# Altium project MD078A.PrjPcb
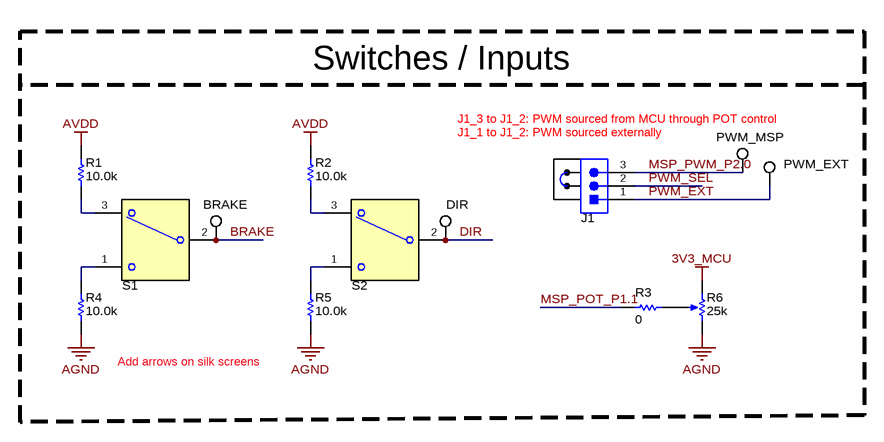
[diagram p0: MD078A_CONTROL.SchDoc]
CopyrightYear: 2023; PCB_Layout: Hong Ze Khor; PCB_Rev: A; PRJ_Customer: Public Release; PRJ_Engineer: Hong Ze Khor; PRJ_Number: MD078; PRJ_Title: MCT8314ZEVM; ProjectVariant: EVM_Orderable; SCH_Rev: A; TechSupport: http://www.ti.com/support; TID: N/A
5 sheets, 157 parts. Net scope: global (net labels, ports and power ports of the same name join across sheets).
Board file: MD078A.PcbDoc
Sheets:
  MD078A_CONTROL.SchDoc
  MD078A_DRIVER.SchDoc
  MD078A_HARDWARE.SchDoc
  MD078A_INTERFACE.SchDoc
  MD078A_POWER_AND_CONNECTORS.SchDoc

## Sheet MD078A_CONTROL.SchDoc
size 431 x 279 mm; Date: Not shown in title block; ApprovedBy: Not shown in title block; CheckedBy: Not shown in title block; Author: Not shown in title block; CompanyName: Not shown in title block; Engineer: Not shown in title block; Organization: Not shown in title block; Address1: Not shown in title block; Address2: Not shown in title block; Address3: Not shown in title block; Address4: Not shown in title block; DocumentNumber: 1; Revision: Use project parameter SCH_Rev; SheetNumber: 2; SheetTotal: 5; PageSetup: Record=PageOptions¦CenterHorizontal=True¦CenterVertical=True¦PrintScale=1.00¦XCorrection=1.00¦YCorrection=1.00¦PrintKind=0¦BorderSize=5000000¦LeftOffset=0¦BottomOffset=0¦Orientation=2¦PaperLength=1000¦PaperWidth=1000¦Scale=100¦PaperSource=15¦PrintQuality=600¦MediaType=1¦DitherType=10¦PaperKind=Letter¦PrintScaleMode=1

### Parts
J1  Header_3x1  [PBC03SAAN]  (value not drawn)
R1  ValueDisplayed: 10.0k  [0603]  (hidden comment: RC0603FR-0710KL)
R2  ValueDisplayed: 10.0k  [0603]  (hidden comment: RC0603FR-0710KL)
R3  ValueDisplayed: 0  [0603L]  (hidden comment: ERJ-3GEY0R00V)
R4  ValueDisplayed: 10.0k  [0603]  (hidden comment: RC0603FR-0710KL)
R5  ValueDisplayed: 10.0k  [0603]  (hidden comment: RC0603FR-0710KL)
R6  value 25k  [Bourns_3352T]  (hidden comment: 3352T-1-253LF)
S1  SW_SPDT_COM2_1_3  [SW_B12AP]  (value not drawn)
S2  SW_SPDT_COM2_1_3  [SW_B12AP]  (value not drawn)
SH-J1  SNT-100-BK-G  [SNT-100-BK-G]  (value not drawn)
TP1  PWM_MSP  [Keystone5002]
TP2  PWM_EXT  [Keystone5002]
TP3  BRAKE  [Keystone5002]
TP4  DIR  [Keystone5002]

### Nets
3V3_MCU: R6.1(CCW)
AGND: R4.1 R5.1 R6.3(CW)
AVDD: R1.2 R2.2
BRAKE: S1.2(COM) TP3.1
DIR: S2.2(COM) TP4.1
MSP_POT_P1.1: R3.1
MSP_PWM_P2.0: J1.3 TP1.1
PWM_EXT: J1.1 TP2.1
PWM_SEL: J1.2
NetR1_1: R1.1 S1.3
NetR2_1: R2.1 S2.3
NetR3_2: R3.2 R6.2(WIPER)
NetR4_2: R4.2 S1.1
NetR5_2: R5.2 S2.1

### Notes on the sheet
- Switches / Inputs
- J1_1 to J1_2: PWM sourced externally
- J1_3 to J1_2: PWM sourced from MCU through POT control
- Add arrows on silk screens

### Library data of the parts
J1 = CMP-0002334-1: Header, 100mil, 3x1, Gold, TH; Manufacturer: Sullins Connector Solutions; CNHeader: TRUE; CT: FALSE; Green_Lifecycle: Not Set; Green_REACh: Incomplete
R1 R2 R4 R5 = CMP-0022746-5: RES, 10.0 k, 1%, 0.1 W, 0603; Manufacturer: Yageo; Power_W: 100mW; TempCo: 100 ppm/C; Value_Code: 10k0; Value: 10.0k; EIA_Code: E96; Res_ohm: 10k; SizeX_mm: 1.6; SizeY_mm: 0.8; SizeZ_mm: 1; Value2: 0.1W; SizeArea_mm2: 1.28; AEC Qualified: N; VDC_V: 75V; AEC Category: Q200; SizeAreaWB_mm2: 4.68
R3 = CMP-0025874-4: RES, 0, 5%, 0.1 W, AEC-Q200 Grade 0, 0603; Manufacturer: Panasonic; Power_W: 100mW; TempCo: 600 ppm/C; Value_Code: 0000; Value: 0; EIA_Code: E24; SizeX_mm: 1.6; SizeY_mm: 0.8; SizeZ_mm: 1; Value2: 0.1W; SizeArea_mm2: 1.28; AEC Qualified: Y; VDC_V: 50V; AEC Category: Q200; SizeAreaWB_mm2: 4.68
R6 = CMP-0001776-2: Trimmer Potentiometer, 25kohm, 0.5W, TH; Manufacturer: Bourns
S1 S2 = CMP-0002155-2: SWITCH TOGGLE SPDT 0.4VA 28V; PartNumber: B12AP; Manufacturer: NKK Switches; SwitchFunction: On-On; PositionCount: 2; CurrentRating_mA: 100A
SH-J1 = CMP-0003623-3: Shunt, 100mil, Gold plated, Black; Alternate PartNumber: 969102-0000-DA; Manufacturer: Samtec; Alternate Manufacturer: 3M; Value: 1x2
TP1-TP4 = CMP-0055139-2: Test Point, Miniature, White, TH; Manufacturer: Keystone Electronics; CNHeader: FALSE; Green_Lifecycle: Active; Green_REACh: Passed; ContactFinish: Silver; CT: TRUE

## Sheet MD078A_DRIVER.SchDoc
size 431 x 279 mm; Date: Not shown in title block; ApprovedBy: Not shown in title block; CheckedBy: Not shown in title block; Author: Not shown in title block; CompanyName: Not shown in title block; Engineer: Not shown in title block; Organization: Not shown in title block; Address1: Not shown in title block; Address2: Not shown in title block; Address3: Not shown in title block; Address4: Not shown in title block; DocumentNumber: 2; Revision: Use project parameter SCH_Rev; SheetNumber: 3; SheetTotal: 5; PageSetup: Record=PageOptions¦CenterHorizontal=True¦CenterVertical=True¦PrintScale=1.00¦XCorrection=1.00¦YCorrection=1.00¦PrintKind=0¦BorderSize=5000000¦LeftOffset=0¦BottomOffset=0¦Orientation=2¦PaperLength=1000¦PaperWidth=1000¦Scale=100¦PaperSource=15¦PrintQuality=600¦MediaType=1¦DitherType=10¦PaperKind=Letter¦PrintScaleMode=1
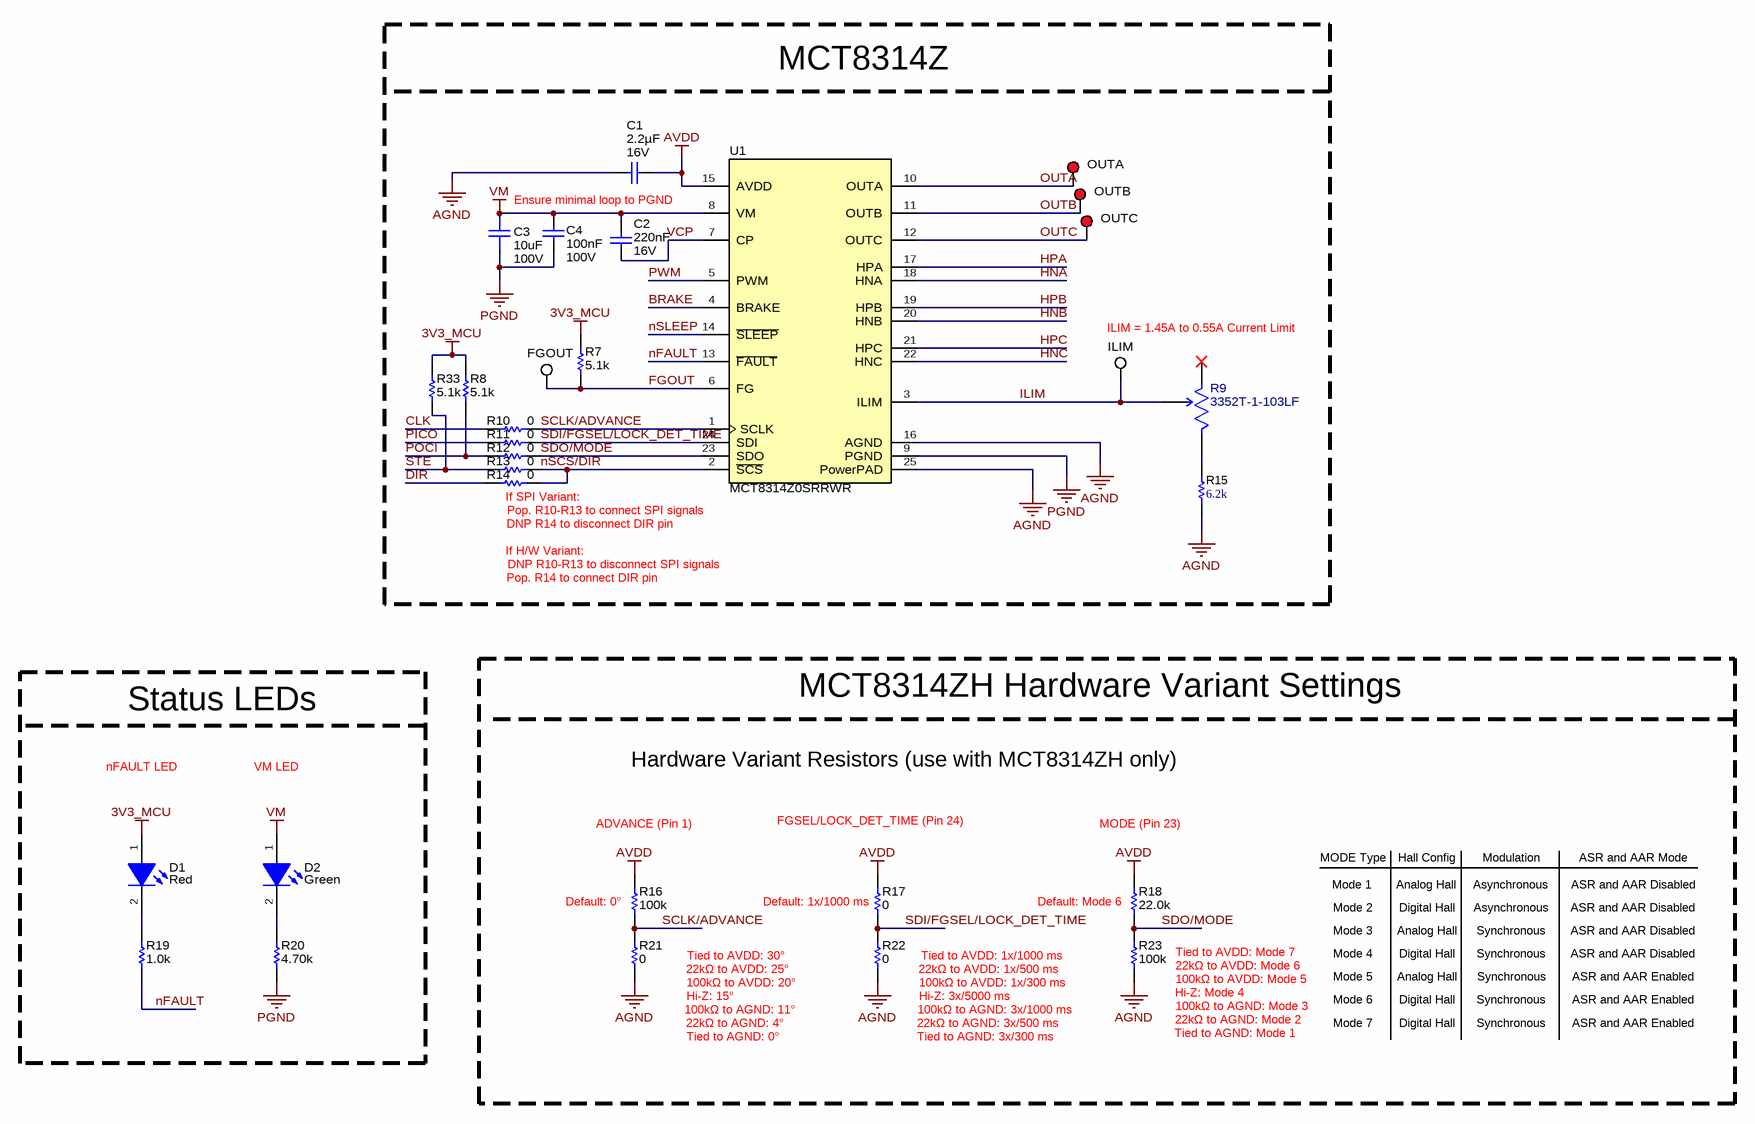
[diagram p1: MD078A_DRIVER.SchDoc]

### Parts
C1  VDC_V: 16V  Cap_F: 2.2µF  [0603L]  (hidden comment: GRM188Z71C225KE43)
C2  Cap_F: 220nF  VDC_V: 16V  [0603]  (hidden comment: C0603C224K4RACTU)
C3  ValueDisplayed: 10uF  VDC_V: 100V  [FP-C3216X6S2A106K160AC_1206-MFG]  (hidden comment: C3216X6S2A106K160AC)
C4  Cap_F: 100nF  VDC_V: 100V  [0603]  (hidden comment: GCJ188R72A104KA01D)
D1  value Red  [LED_LTST-C170_Red]  (hidden comment: LTST-C170KRKT)
D2  value Green  [LTST-C170KGKT_Green]  (hidden comment: LTST-C170KGKT)
R7  ValueDisplayed: 5.1k  [0603L]  (hidden comment: RC0603JR-075K1L)
R8  ValueDisplayed: 5.1k  [0603L]  (hidden comment: RC0603JR-075K1L)
R9  3352T-1-103LF  [Bourns_3352T]
R10  ValueDisplayed: 0  [0603L]  (hidden comment: ERJ-3GEY0R00V)
R11  ValueDisplayed: 0  [0603L]  (hidden comment: ERJ-3GEY0R00V)
R12  ValueDisplayed: 0  [0603L]  (hidden comment: ERJ-3GEY0R00V)
R13  ValueDisplayed: 0  [0603L]  (hidden comment: ERJ-3GEY0R00V)
R14  ValueDisplayed: 0  [0603L]  (hidden comment: ERJ-3GEY0R00V)
R15  ValueDisplayed: 6.2k  [0603]  (hidden comment: RC0603JR-076K2L)
R16  ValueDisplayed: 100k  [0603L]  (hidden comment: ERA-3AEB104V)
R17  ValueDisplayed: 0  [0603L]  (hidden comment: ERJ-3GEY0R00V)
R18  ValueDisplayed: 22.0k  [0603L]  (hidden comment: ERJ-3EKF2202V)
R19  ValueDisplayed: 1.0k  [0603L]  (hidden comment: RC0603JR-071KL)
R20  ValueDisplayed: 4.70k  [0603L]  (hidden comment: RT0603BRD074K7L)
R21  ValueDisplayed: 0  [0603L]  (hidden comment: ERJ-3GEY0R00V)
R22  ValueDisplayed: 0  [0603L]  (hidden comment: ERJ-3GEY0R00V)
R23  ValueDisplayed: 100k  [0603L]  (hidden comment: ERA-3AEB104V)
R33  ValueDisplayed: 5.1k  [0603L]  (hidden comment: RC0603JR-075K1L)
TP5  OUTA  [Keystone5000]
TP6  OUTB  [Keystone5000]
TP7  OUTC  [Keystone5000]
TP8  ILIM  [Keystone5002]
TP9  FGOUT  [Keystone5002]
U1  MCT8314Z0SRRWR  [RRW0024A-MFG]

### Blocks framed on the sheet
MCT8314Z: C1-C4 R7-R15 R33 TP5-TP9 U1
MCT8314ZH Hardware Variant Settings: R16-R18 R21-R23
Status LEDs: D1 D2 R19 R20

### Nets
3V3_MCU: D1.1(A) R7.2 R8.2 R33.2
AGND: C1.2 R15.1 R21.1 R22.1 R23.1 U1.16(AGND) U1.25(PowerPAD)
AVDD: C1.1 R16.2 R17.2 R18.2 U1.15(AVDD)
PGND: C3.1 C4.2 R20.1 U1.9(PGND)
VM: C2.1 C3.2 C4.1 D2.1(A) U1.8(VM)
BRAKE: U1.4(BRAKE)
CLK: R10.1
DIR: R14.1
FGOUT: R7.1 TP9.1 U1.6(FG)
HNA: U1.18(HNA)
HNB: U1.20(HNB)
HNC: U1.22(HNC)
HPA: U1.17(HPA)
HPB: U1.19(HPB)
HPC: U1.21(HPC)
ILIM: R9.2(WIPER) TP8.1 U1.3(ILIM)
nFAULT: R19.1 U1.13(~{FAULT})
nSCS/DIR: R13.2 R14.2 U1.2(~{SCS})
nSLEEP: U1.14(~{SLEEP})
OUTA: TP5.1 U1.10(OUTA)
OUTB: TP6.1 U1.11(OUTB)
OUTC: TP7.1 U1.12(OUTC)
PICO: R11.1
POCI: R8.1 R12.1
PWM: U1.5(PWM)
SCLK/ADVANCE: R10.2 R16.1 R21.2 U1.1(SCLK)
SDI/FGSEL/LOCK_DET_TIME: R11.2 R17.1 R22.2 U1.24(SDI)
SDO/MODE: R12.2 R18.1 R23.2 U1.23(SDO)
STE: R13.1 R33.1
VCP: C2.2 U1.7(CP)
NetD1_2: D1.2(K) R19.2
NetD2_2: D2.2(K) R20.2
NetR9_1: R9.1(CCW) R15.2

Not connected (* = marked no-connect by the designer): R9 3(CW)*

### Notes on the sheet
- Ensure minimal loop to PGND
- ILIM = 1.45A to 0.55A Current Limit
- (near R14) If SPI Variant:
- DNP R14 to disconnect DIR pin
- Pop. R10-R13 to connect SPI signals
- If H/W Variant:
- Pop. R14 to connect DIR pin
- DNP R10-R13 to disconnect SPI signals
- nFAULT LED
- VM LED
- Hardware Variant Resistors (use with MCT8314ZH only)
- ADVANCE (Pin 1)
- FGSEL/LOCK_DET_TIME (Pin 24)
- MODE (Pin 23)
- MODE Type
- Hall Config
- Modulation
- ASR and AAR Mode
- (near R16) Default: 0°
- (near R17) Default: 1x/1000 ms
- (near R18) Default: Mode 6
- Mode 1
- Mode 2
- Mode 3
- Analog Hall
- Digital Hall
- Asynchronous
- Synchronous
- ASR and AAR Disabled
- (near R21) Hi-Z: 15°
- Tied to AVDD: 30°
- 22kΩ to AVDD: 25°
- 100kΩ to AVDD: 20°
- (near R22) Hi-Z: 3x/5000 ms
- Tied to AVDD: 1x/1000 ms
- 22kΩ to AVDD: 1x/500 ms
- 100kΩ to AVDD: 1x/300 ms
- (near R23) Hi-Z: Mode 4
- Tied to AVDD: Mode 7
- 22kΩ to AVDD: Mode 6
- (near R23) 100kΩ to AVDD: Mode 5
- Mode 4
- Mode 6
- Mode 5
- ASR and AAR Enabled
- Tied to AGND: 0°
- 22kΩ to AGND: 4°
- 100kΩ to AGND: 11°
- Tied to AGND: 3x/300 ms
- 22kΩ to AGND: 3x/500 ms
- 100kΩ to AGND: 3x/1000 ms
- Tied to AGND: Mode 1
- 22kΩ to AGND: Mode 2
- 100kΩ to AGND: Mode 3
- Mode 7

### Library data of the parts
C1 = CMP-0007499-4: CAP, CERM, 2.2 uF, 16 V, +/- 10%, X7R, 0603; Manufacturer: MuRata; TaMin_C: -55°C; Polarized: N; SizeAreaWB_mm2: 4.68; Value1: Unknown; U/M: EA; Value: 2.2uF; TaMax_C: 125°C; SizeZ_mm: 1; SizeX_mm: 1.6; SizeY_mm: 0.8; Cap_Case: 0603; SizeArea_mm2: 1.28; AEC Category: Q200
C2 = CMP-0006903-4: CAP, CERM, 0.22 uF, 16 V, +/- 10%, X7R, 0603; Manufacturer: Kemet; TaMin_C: -55°C; Polarized: N; SizeAreaWB_mm2: 4.68; Value1: Unknown; U/M: EA; Value: 0.22uF; TaMax_C: 125°C; SizeZ_mm: 1; SizeX_mm: 1.6; SizeY_mm: 0.8; SizeArea_mm2: 1.28; AEC Category: Q200
C3 = CMP-0098402-1: 10 µF ±10% 100V Ceramic Capacitor X6S 1206 (3216 Metric); Manufacturer: TDK; AEC Qualified: No; Cap_F: 10µF; SizeZ_mm: 1.9mm; TempCo: 22%; Value: 10µF
C4 = CMP-0064935-4: CAP, CERM, 0.1 uF, 100 V,+/- 10%, X7R, AEC-Q200 Grade 1, 0603; Manufacturer: MuRata; TaMin_C: -55°C; Polarized: N; SizeAreaWB_mm2: 4.68; Value1: Unknown; U/M: EA; Value: 0.1uF; TaMax_C: 125°C; SizeZ_mm: 1; SizeX_mm: 1.6; SizeY_mm: 0.8; SizeArea_mm2: 1.28; AEC Qualified: Y; AEC Category: Q200
D1 = CMP-0002829-3: LED, Red, SMD; Manufacturer: Lite-On; Io_A: 20mA; SizeAreaWB_mm2: 6.75; Value1: W; SizeZ_mm: 1.2; SizeX_mm: 2; SizeY_mm: 1.25; Vf_V: 2V; SizeArea_mm2: 2.5; Type: AlInGaP
D2 = CMP-0002888-2: LED, Green, SMD; Manufacturer: Lite-On; Io_A: 20mA; Value1: W; Vf_V: 2V; Type: AlInGaP
R7 R8 R33 = CMP-0025932-5: RES, 5.1 k, 5%, 0.1 W, 0603; Manufacturer: Yageo; Power_W: 100mW; TempCo: 100 ppm/C; Value_Code: 5k10; Value: 5.1k; EIA_Code: E24; SizeX_mm: 1.6; SizeY_mm: 0.8; SizeZ_mm: 1; Value2: 0.1W; SizeArea_mm2: 1.28; AEC Qualified: N; VDC_V: 75V; AEC Category: Q200; SizeAreaWB_mm2: 4.68
R9 = CMP-0093882-3: 10 kOhms 0.5W, 1/2W Through Hole Thumbwheel Potentiometer Top Adjustment; Manufacturer: Bourns; Value: 10kΩ; Voltage: 250V; TempCo: 100ppm/°C; Standoff Height: 0.64mm; Tolerance_%: 20%; Power: 500mW; AEC Qualified: No; SizeZ_mm: 4.32mm
R10-R14 R17 R21 R22 = CMP-0025874-4: as R3 on sheet MD078A_CONTROL
R15 = CMP-0025937-5: RES, 6.2 k, 5%, 0.1 W, 0603; Manufacturer: Yageo; Power_W: 100mW; TempCo: 100 ppm/C; Value_Code: 6k20; Value: 6.2k; EIA_Code: E24; SizeX_mm: 1.6; SizeY_mm: 0.8; SizeZ_mm: 1; Value2: 0.1W; SizeArea_mm2: 1.28; AEC Qualified: N; VDC_V: 75V; AEC Category: Q200; SizeAreaWB_mm2: 4.68
R16 R23 = CMP-0023363-3: RES, 100 k, 0.1%, 0.1 W, AEC-Q200 Grade 0, 0603; Manufacturer: Panasonic; Power_W: 100mW; TempCo: 25 ppm/C; U/M: EA; Value: 100k; EIA_Code: E192; SizeX_mm: 1.6; SizeY_mm: 0.8; SizeZ_mm: 1; Value2: 0.1W; SizeArea_mm2: 1.28; AEC Qualified: Y; VDC_V: 75V; AEC Grade: 0; AEC Category: Q200
R18 = CMP-0022692-3: RES, 22.0 k, 1%, 0.1 W, AEC-Q200 Grade 0, 0603; Manufacturer: Panasonic; Power_W: 100mW; TempCo: 100 ppm/C; Value_Code: 22k0; U/M: EA; Value: 22.0k; Res_ohm: 22k; SizeX_mm: 1.6; SizeY_mm: 0.8; SizeZ_mm: 1; Value2: 0.1W; SizeArea_mm2: 1.28; AEC Qualified: Y; VDC_V: 50V; AEC Grade: 0; AEC Category: Q200
R19 = CMP-0025899-5: RES, 1.0 k, 5%, 0.1 W, 0603; Manufacturer: Yageo; Power_W: 100mW; TempCo: 100 ppm/C; Value_Code: 1k00; Value: 1.0k; EIA_Code: E24; Res_ohm: 1k; SizeX_mm: 1.6; SizeY_mm: 0.8; SizeZ_mm: 1; Value2: 0.1W; SizeArea_mm2: 1.28; AEC Qualified: N; VDC_V: 75V; AEC Category: Q200; SizeAreaWB_mm2: 4.68
R20 = CMP-0024300-2: RES, 4.70 k, 0.1%, 0.1 W, 0603; Manufacturer: Yageo America; Power_W: 100mW; TempCo: 25 ppm/C; Value_Code: 4k70; U/M: EA; Value: 4.70k; EIA_Code: E192; Res_ohm: 4.7k; SizeX_mm: 1.6; SizeY_mm: 0.8; SizeZ_mm: 1; Value2: 0.1W; SizeArea_mm2: 1.28; VDC_V: 75V; AEC Category: Q200
TP5-TP7 = CMP-0055137-2: Test Point, Miniature, Red, TH; Manufacturer: Keystone Electronics; ContactFinish: Silver; CNHeader: FALSE; CT: TRUE; Green_Lifecycle: Active; Green_REACh: Passed
TP8 TP9 = CMP-0055139-2: as TP1 on sheet MD078A_CONTROL
U1 = CMP-0034379-1: Manufacturer: Texas Instruments; SizeZ_mm: 0.8mm; Standoff Height: 0mm

## Sheet MD078A_HARDWARE.SchDoc
size 431 x 279 mm; Date: Not shown in title block; ApprovedBy: Not shown in title block; CheckedBy: Not shown in title block; Author: Not shown in title block; CompanyName: Not shown in title block; Engineer: Not shown in title block; Organization: Not shown in title block; Address1: Not shown in title block; Address2: Not shown in title block; Address3: Not shown in title block; Address4: Not shown in title block; DocumentNumber: 3; Revision: Use project parameter SCH_Rev; SheetNumber: 5; SheetTotal: 5; PageSetup: Record=PageOptions¦CenterHorizontal=True¦CenterVertical=True¦PrintScale=1.00¦XCorrection=1.00¦YCorrection=1.00¦PrintKind=0¦BorderSize=5000000¦LeftOffset=0¦BottomOffset=0¦Orientation=2¦PaperLength=1000¦PaperWidth=1000¦Scale=100¦PaperSource=15¦PrintQuality=600¦MediaType=1¦DitherType=10¦PaperKind=Letter¦PrintScaleMode=1
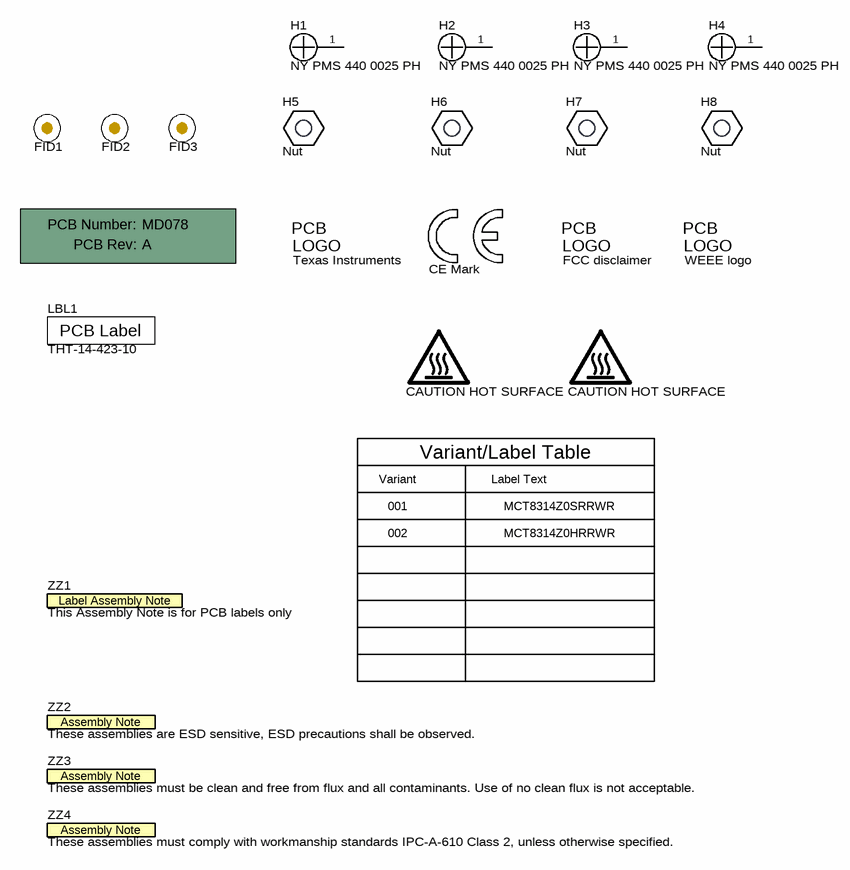
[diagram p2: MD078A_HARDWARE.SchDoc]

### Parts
!PCB1  Printed Circuit Board  (value not drawn)  (mechanical)
FID1  Fiducial  [Fiducial10-20]  (value not drawn)
FID2  Fiducial  [Fiducial10-20]  (value not drawn)
FID3  Fiducial  [Fiducial10-20]  (value not drawn)
H1  NY PMS 440 0025 PH  [NY PMS 440 0025 PH]
H2  NY PMS 440 0025 PH  [NY PMS 440 0025 PH]
H3  NY PMS 440 0025 PH  [NY PMS 440 0025 PH]
H4  NY PMS 440 0025 PH  [NY PMS 440 0025 PH]
H5  Nut  [Keystone_1902C]
H6  Nut  [Keystone_1902C]
H7  Nut  [Keystone_1902C]
H8  Nut  [Keystone_1902C]
LBL1  THT-14-423-10  [Label_650x200]
Logo1  CE Mark  [CE_Mark_5mm]  (no BOM)
Logo2  Texas Instruments  [TI_Stacked_Overlay_Small]  (no BOM)
Logo3  FCC disclaimer  [FCC_disclaimer]  (no BOM)
Logo4  WEEE logo  [WEEE_Minimum]  (no BOM)
LOGO5  CAUTION HOT SURFACE  [IEC_HotSurface_Small]  (no BOM)
LOGO6  CAUTION HOT SURFACE  [IEC_HotSurface_Small]  (no BOM)
ZZ1  This Assembly Note is for PCB labels only  [AssemblyNoteLabel]  (no BOM)
ZZ2  These assemblies are ESD sensitive, ESD precautions shall be observed.  [AssemblyNote]  (no BOM)
ZZ3  These assemblies must be clean and free from flux and all contaminants. Use of no clean flux is not acceptable.  [AssemblyNote]  (no BOM)
ZZ4  These assemblies must comply with workmanship standards IPC-A-610 Class 2, unless otherwise specified.  [AssemblyNote]  (no BOM)

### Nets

Not connected (* = marked no-connect by the designer): H1 1; H2 1; H3 1; H4 1

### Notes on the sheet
- Variant
- Variant/Label Table
- Label Text
- 001
- 002
- MCT8314Z0SRRWR
- MCT8314Z0HRRWR

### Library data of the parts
!PCB1 = CMP-0003618-2: Manufacturer: Any; PartNumber: MD078
FID1-FID3 = CMP-0077181-1: Fiducial mark.  There is nothing to buy or mount.
H1-H4 = CMP-0003617-1: Machine Screw, Round, #4-40 x 1/4, Nylon, Philips panhead; Manufacturer: B&F Fastener Supply; CompType: Hardware
H5-H8 = CMP-0003610-1: Standoff, Hex, 0.5"L #4-40 Nylon; Manufacturer: Keystone; PartNumber: 1902C; CompType: Hardware
LBL1 = CMP-0003625-1: Manufacturer: Brady
Logo1 = CMP-0074844-1: SymbolCreator: a0412235
Logo2 = CMP-0074838-1: Texas Instrument Corporate Signature; SymbolCreator: a0412235; Lib Reference: TI_Logo; Library Reference: Logo
Logo3 = CMP-0074847-1: FCC_disclaimer; Library Reference: Logo
Logo4 = CMP-0074769-3: Manufacturer: Texas Instruments; CompType: IC; AEC Category: Q200
LOGO5 LOGO6 = CMP-0074837-2: IEC 61010-1 Hot Surface Warning; Manufacturer: Texas Instruments; SymbolCreator: a0412235; CompType: IC; AEC Category: Q200
ZZ1 = CMP-0003616-3
ZZ2 = CMP-0077236-1
ZZ3 = CMP-0077237-1
ZZ4 = CMP-0077238-1

## Sheet MD078A_INTERFACE.SchDoc
size 431 x 279 mm; Date: Not shown in title block; ApprovedBy: Not shown in title block; CheckedBy: Not shown in title block; Author: Not shown in title block; CompanyName: Not shown in title block; Engineer: Not shown in title block; Organization: Not shown in title block; Address1: Not shown in title block; Address2: Not shown in title block; Address3: Not shown in title block; Address4: Not shown in title block; DocumentNumber: 4; Revision: Use project parameter SCH_Rev; SheetNumber: 1; SheetTotal: 5; PageSetup: Record=PageOptions¦CenterHorizontal=True¦CenterVertical=True¦PrintScale=1.00¦XCorrection=1.00¦YCorrection=1.00¦PrintKind=0¦BorderSize=5000000¦LeftOffset=0¦BottomOffset=0¦Orientation=2¦PaperLength=1000¦PaperWidth=1000¦Scale=100¦PaperSource=15¦PrintQuality=600¦MediaType=1¦DitherType=10¦PaperKind=Letter¦PrintScaleMode=1
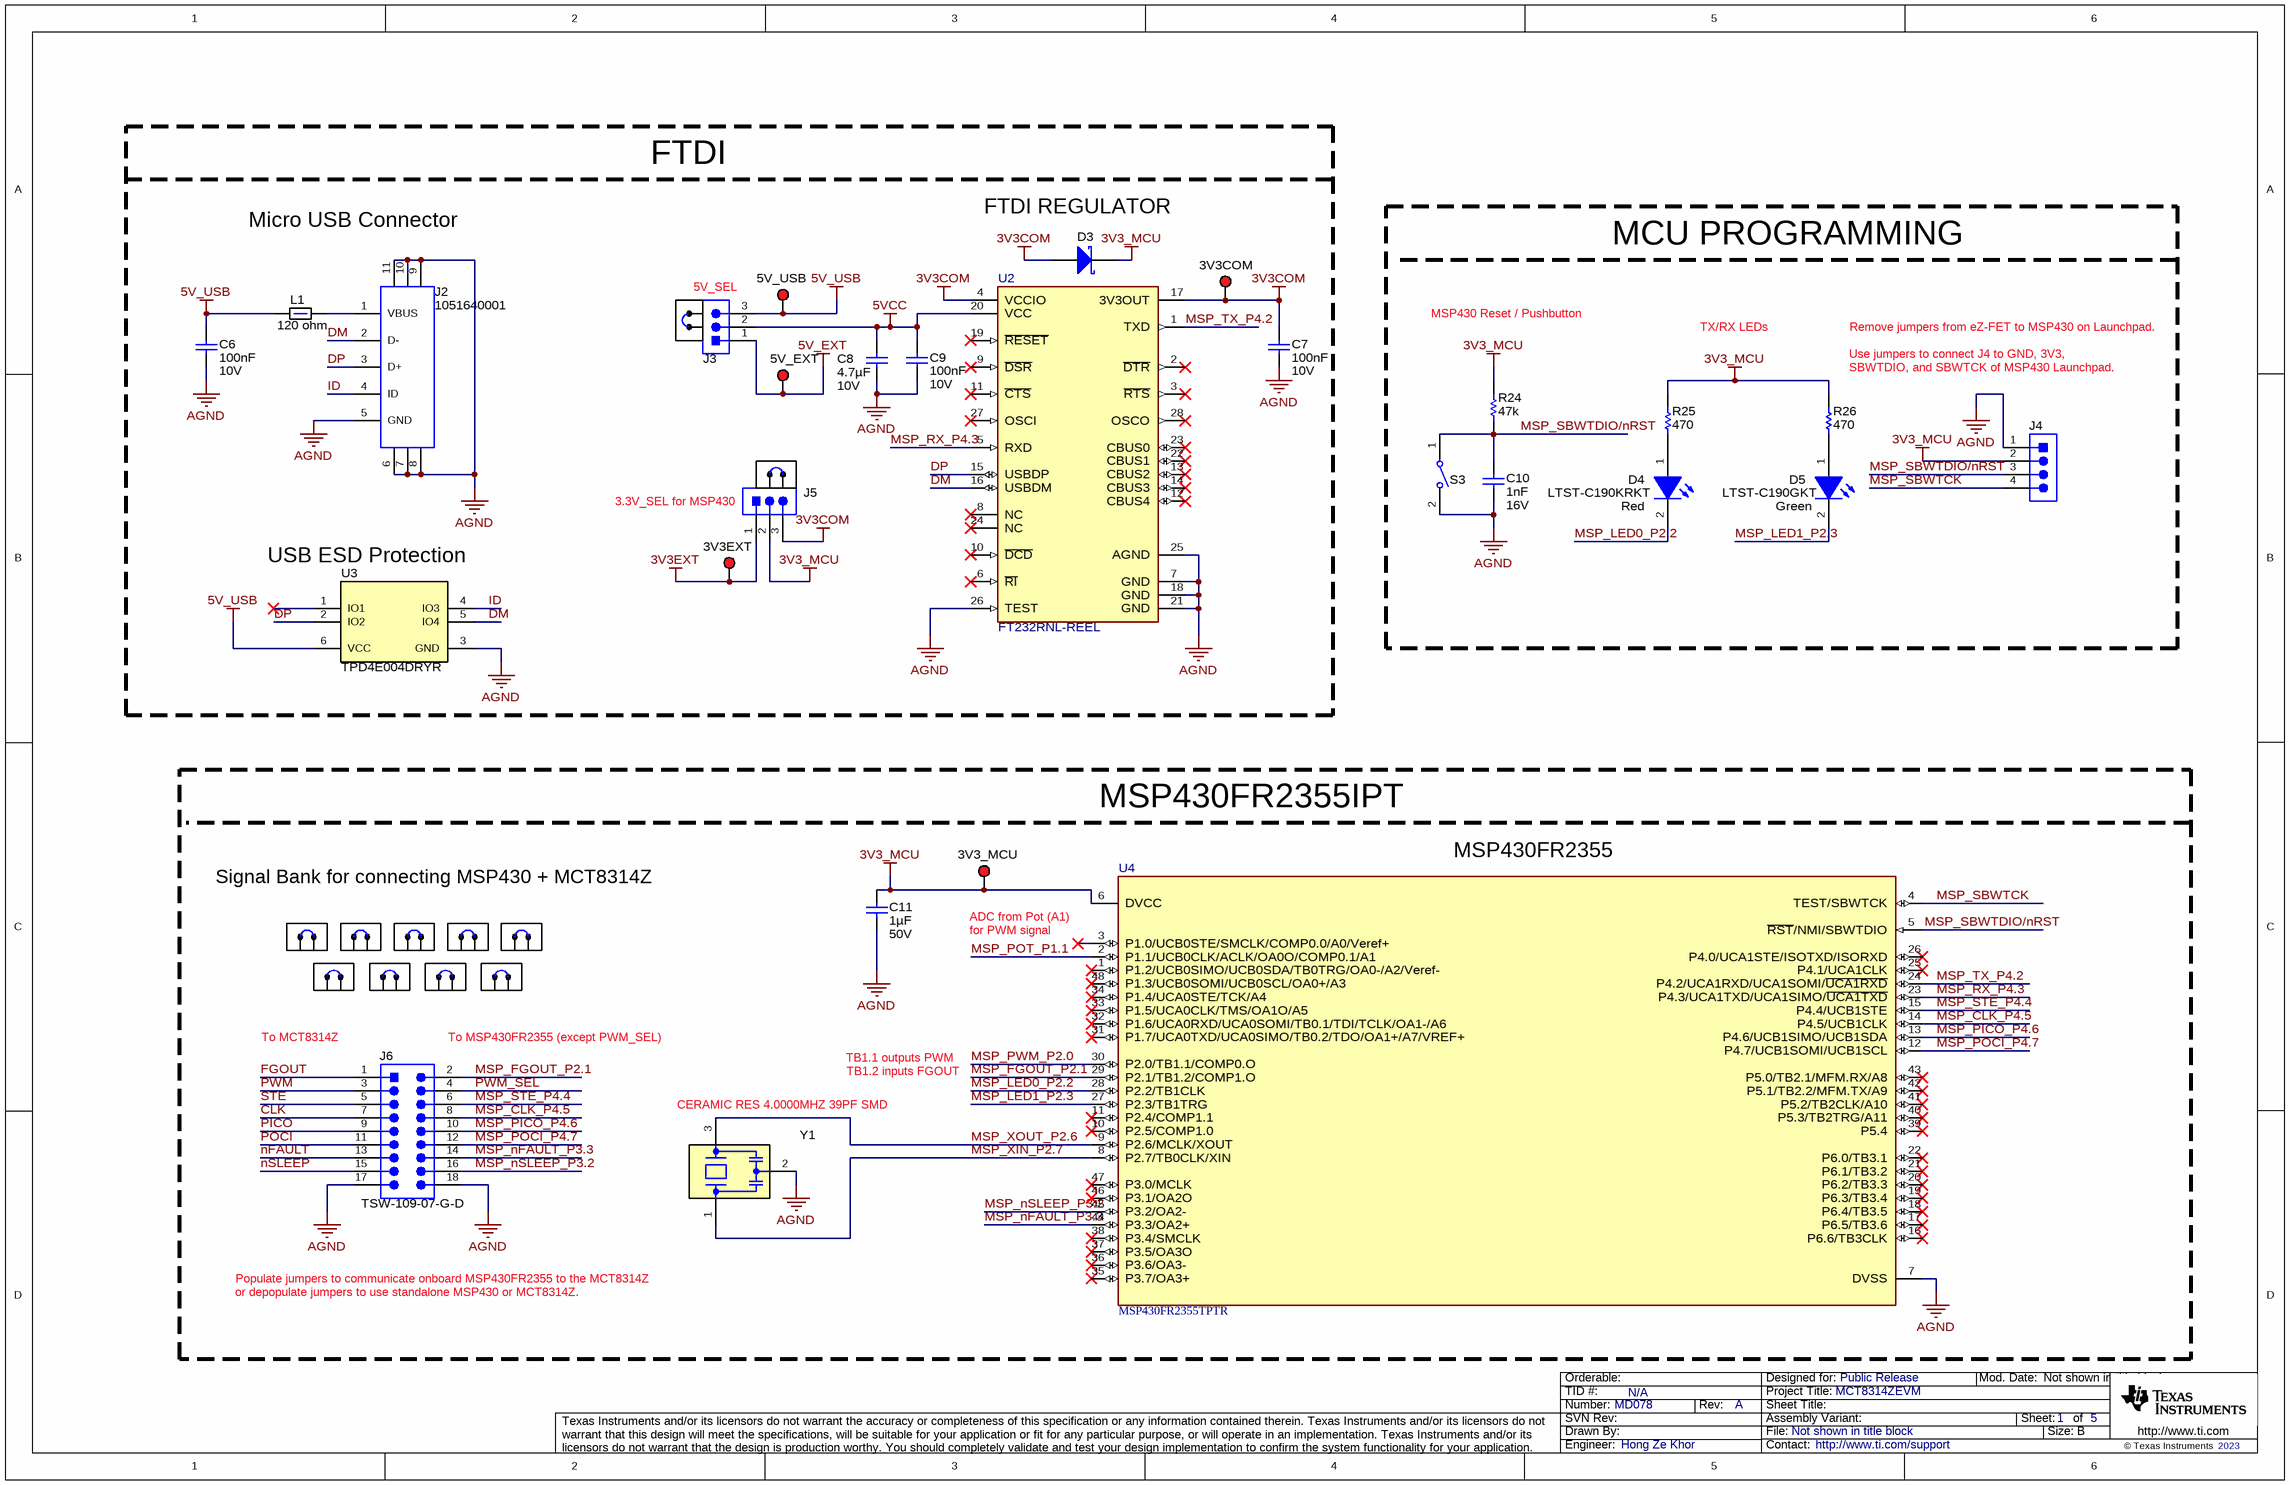
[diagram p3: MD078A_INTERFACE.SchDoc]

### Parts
C6  Cap_F: 100nF  VDC_V: 10V  [0603L]  (hidden comment: C0603C104K8RACTU)
C7  Cap_F: 100nF  VDC_V: 10V  [0603]  (hidden comment: C0603C104K8RACTU)
C8  Cap_F: 4.7µF  VDC_V: 10V  [0603L]  (hidden comment: GRM188Z71A475ME15D)
C9  Cap_F: 100nF  VDC_V: 10V  [0603L]  (hidden comment: C0603C104K8RACTU)
C10  Cap_F: 1nF  VDC_V: 16V  [0603L]  (hidden comment: 885012206034)
C11  Cap_F: 1µF  VDC_V: 50V  [0805_HV]  (hidden comment: C0805C105K5RACTU)
D3  BAT165E6327HTSA1  [SOD-323]  (value not drawn)
D4  LTST-C190KRKT  value Red  [LED_LTST-C190_Red]
D5  LTST-C190GKT  value Green  [LED_LTST-C190]
J2  1051640001  [Molex_1051640001]
J3  Header_3x1  [PBC03SAAN]  (value not drawn)
J4  TSW-104-07-G-S  [TSW-104-07-G-S]  (value not drawn)
J5  Header_3x1  [PBC03SAAN]  (value not drawn)
J6  TSW-109-07-G-D  [Samtec_TSW-109-07-G-D]
L1  DCR_ohm: 120 ohm  [0603L]  (hidden comment: BLM18SG121TZ1D)
R24  ValueDisplayed: 47k  [0603L]  (hidden comment: RC0603JR-0747KL)
R25  ValueDisplayed: 470  [0603L]  (hidden comment: RC0603JR-07470RL)
R26  ValueDisplayed: 470  [0603L]  (hidden comment: RC0603JR-07470RL)
S3  SW_SPST-single  [SW_434121025816]  (value not drawn)
SH-J2  SNT-100-BK-G  [SNT-100-BK-G]  (value not drawn)
SH-J3  SNT-100-BK-G  [SNT-100-BK-G]  (value not drawn)
SH-J4  SNT-100-BK-G  [SNT-100-BK-G]  (value not drawn)
SH-J5  SNT-100-BK-G  [SNT-100-BK-G]  (value not drawn)
SH-J6  SNT-100-BK-G  [SNT-100-BK-G]  (value not drawn)
SH-J7  SNT-100-BK-G  [SNT-100-BK-G]  (value not drawn)
SH-J8  SNT-100-BK-G  [SNT-100-BK-G]  (value not drawn)
SH-J9  SNT-100-BK-G  [SNT-100-BK-G]  (value not drawn)
SH-J10  SNT-100-BK-G  [SNT-100-BK-G]  (value not drawn)
SH-J11  SNT-100-BK-G  [SNT-100-BK-G]  (value not drawn)
SH-J12  SNT-100-BK-G  [SNT-100-BK-G]  (value not drawn)
TP10  3V3COM  [Keystone5000]
TP11  5V_USB  [Keystone5000]
TP12  5V_EXT  [Keystone5000]
TP13  3V3EXT  [Keystone5000]
TP14  3V3_MCU  [Keystone5000]
U2  FT232RNL-REEL  [FP-FT232RNL-REEL_SSOP28-MFG]
U3  TPD4E004DRYR  [DRY0006A]
U4  MSP430FR2355TPTR  [PT0048A-MFG]
Y1  CSTCR4M00G55B-R0  [Murata_CSTCR_G]  (value not drawn)

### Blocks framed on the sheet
FTDI: C6-C9 D3 J2 J3 J5 L1 SH-J2 SH-J3 TP10-TP13 U2 U3
MCU PROGRAMMING: C10 D4 D5 J4 R24-R26 S3
MSP430FR2355IPT: C11 J6 SH-J4-SH-J12 TP14 U4 Y1

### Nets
3V3_MCU: C11.1 D3.1(K) J4.2 J5.2 R24.2 R25.2 R26.2 TP14.1 U4.6(DVCC)
3V3COM: C7.1 D3.2(A) J5.3 TP10.1 U2.4(VCCIO) U2.17(3V3OUT)
3V3EXT: J5.1 TP13.1
5V_EXT: J3.1 TP12.1
5V_USB: C6.1 J3.3 L1.1 TP11.1 U3.6(VCC)
5VCC: C8.2 C9.1 J3.2 U2.20(VCC)
AGND: C6.2 C7.2 C8.1 C9.2 C10.2 C11.2 J2.5(GND) J2.6 J2.7 J2.8 J2.9 J2.10 J2.11 J4.1 J6.17 J6.18 S3.2 U2.7(GND) U2.18(GND) U2.21(GND) U2.25(AGND) U2.26(TEST) U3.3(GND) U4.7(DVSS) Y1.2(GND)
CLK: J6.7
DM: J2.2(D-) U2.16(USBDM) U3.5(IO4)
DP: J2.3(D+) U2.15(USBDP) U3.2(IO2)
FGOUT: J6.1
ID: J2.4(ID) U3.4(IO3)
MSP_CLK_P4.5: J6.8 U4.14(P4.5/UCB1CLK)
MSP_FGOUT_P2.1: J6.2 U4.29(P2.1/TB1.2/COMP1.O)
MSP_LED0_P2.2: D4.2(K) U4.28(P2.2/TB1CLK)
MSP_LED1_P2.3: D5.2(K) U4.27(P2.3/TB1TRG)
MSP_nFAULT_P3.3: J6.14 U4.44(P3.3/OA2+)
MSP_nSLEEP_P3.2: J6.16 U4.45(P3.2/OA2-)
MSP_PICO_P4.6: J6.10 U4.13(P4.6/UCB1SIMO/UCB1SDA)
MSP_POCI_P4.7: J6.12 U4.12(P4.7/UCB1SOMI/UCB1SCL)
MSP_POT_P1.1: U4.2(P1.1/UCB0CLK/ACLK/OA0O/COMP0.1/A1)
MSP_PWM_P2.0: U4.30(P2.0/TB1.1/COMP0.O)
MSP_RX_P4.3: U2.5(RXD) U4.23(P4.3/UCA1TXD/UCA1SIMO/~{UCA1TXD})
MSP_SBWTCK: J4.4 U4.4(TEST/SBWTCK)
MSP_SBWTDIO/nRST: C10.1 J4.3 R24.1 S3.1 U4.5(~{RST}/NMI/SBWTDIO)
MSP_STE_P4.4: J6.6 U4.15(P4.4/UCB1STE)
MSP_TX_P4.2: U2.1(TXD) U4.24(P4.2/UCA1RXD/UCA1SOMI/~{UCA1RXD})
MSP_XIN_P2.7: U4.8(P2.7/TB0CLK/XIN) Y1.1(In)
MSP_XOUT_P2.6: U4.9(P2.6/MCLK/XOUT) Y1.3(Out)
nFAULT: J6.13
nSLEEP: J6.15
PICO: J6.9
POCI: J6.11
PWM: J6.3
PWM_SEL: J6.4
STE: J6.5
NetD4_1: D4.1(A) R25.1
NetD5_1: D5.1(A) R26.1
NetJ2_1: J2.1(VBUS) L1.2

Not connected (* = marked no-connect by the designer): U2 2(~{DTR})* 3(~{RTS})* 6(~{RI})* 8(NC)* 9(~{DSR})* 10(~{DCD})* 11(~{CTS})* 12(CBUS4)* 13(CBUS2)* 14(CBUS3)* 19(~{RESET})* 22(CBUS1)* 23(CBUS0)* 24(NC)* 27(OSCI)* 28(OSCO)*; U3 1(IO1)*; U4 1(P1.2/UCB0SIMO/UCB0SDA/TB0TRG/OA0-/A2/Veref-)* 3(P1.0/UCB0STE/SMCLK/COMP0.0/A0/Veref+)* 10(P2.5/COMP1.0)* 11(P2.4/COMP1.1)* 16(P6.6/TB3CLK)* 17(P6.5/TB3.6)* 18(P6.4/TB3.5)* 19(P6.3/TB3.4)* 20(P6.2/TB3.3)* 21(P6.1/TB3.2)* 22(P6.0/TB3.1)* 25(P4.1/UCA1CLK)* 26(P4.0/UCA1STE/ISOTXD/ISORXD)* 31(P1.7/UCA0TXD/UCA0SIMO/TB0.2/TDO/OA1+/A7/VREF+)* 32(P1.6/UCA0RXD/UCA0SOMI/TB0.1/TDI/TCLK/OA1-/A6)* 33(P1.5/UCA0CLK/TMS/OA1O/A5)* 34(P1.4/UCA0STE/TCK/A4)* 35(P3.7/OA3+)* 36(P3.6/OA3-)* 37(P3.5/OA3O)* 38(P3.4/SMCLK)* 39(P5.4)* 40(P5.3/TB2TRG/A11)* 41(P5.2/TB2CLK/A10)* 42(P5.1/TB2.2/MFM.TX/A9)* 43(P5.0/TB2.1/MFM.RX/A8)* 46(P3.1/OA2O)* 47(P3.0/MCLK)* 48(P1.3/UCB0SOMI/UCB0SCL/OA0+/A3)*

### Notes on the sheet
- Micro USB Connector
- (near D3) FTDI REGULATOR
- 5V_SEL
- MSP430 Reset / Pushbutton
- TX/RX LEDs
- (near R26) Use jumpers to connect J4 to GND, 3V3,
- SBWTDIO, and SBWTCK of MSP430 Launchpad.
- Remove jumpers from eZ-FET to MSP430 on Launchpad.
- (near J5) 3.3V_SEL for MSP430
- (near U3) USB ESD Protection
- Signal Bank for connecting MSP430 + MCT8314Z
- (near U4) MSP430FR2355
- for PWM signal
- ADC from Pot (A1)
- To MCT8314Z
- To MSP430FR2355 (except PWM_SEL)
- (near Y1) CERAMIC RES 4.0000MHZ 39PF SMD
- TB1.1 outputs PWM
- TB1.2 inputs FGOUT
- or depopulate jumpers to use standalone MSP430 or MCT8314Z.
- Populate jumpers to communicate onboard MSP430FR2355 to the MCT8314Z

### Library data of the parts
C6 C9 = CMP-0006862-5: CAP, CERM, 0.1 uF, 10 V, +/- 10%, X7R, 0603; Manufacturer: Kemet; TaMin_C: -55°C; Polarized: N; SizeAreaWB_mm2: 4.68; Value1: Unknown; U/M: EA; Value: 0.1uF; TaMax_C: 125°C; SizeZ_mm: 1; SizeX_mm: 1.6; SizeY_mm: 0.8; Cap_Case: 0603; SizeArea_mm2: 1.28; AEC Category: Q200
C7 = CMP-0006862-5: CAP, CERM, 0.1 uF, 10 V, +/- 10%, X7R, 0603; Manufacturer: Kemet; TaMin_C: -55°C; Polarized: N; SizeAreaWB_mm2: 4.68; Value1: Unknown; U/M: EA; Value: 0.1uF; TaMax_C: 125°C; SizeZ_mm: 1; SizeX_mm: 1.6; SizeY_mm: 0.8; SizeArea_mm2: 1.28; AEC Category: Q200
C8 = CMP-0007498-4: CAP, CERM, 4.7 uF, 10 V, +/- 20%, X7R, 0603; Manufacturer: MuRata; TaMin_C: -55°C; Polarized: N; SizeAreaWB_mm2: 4.68; Value1: Unknown; U/M: EA; Value: 4.7uF; TaMax_C: 125°C; SizeZ_mm: 1; SizeX_mm: 1.6; SizeY_mm: 0.8; Cap_Case: 0603; SizeArea_mm2: 1.28; AEC Category: Q200
C10 = CMP-0006826-4: CAP, CERM, 1000 pF, 16 V, +/- 10%, X7R, 0603; Manufacturer: Wurth Elektronik; TaMin_C: -55°C; Polarized: N; SizeAreaWB_mm2: 4.68; Value1: Unknown; U/M: EA; Value: 1000pF; TaMax_C: 125°C; SizeZ_mm: 1; SizeX_mm: 1.6; SizeY_mm: 0.8; Cap_Case: 0603; SizeArea_mm2: 1.28; AEC Category: Q200
C11 = CMP-0007730-2: CAP, CERM, 1 uF, 50 V, +/- 10%, X7R, 0805; Manufacturer: Kemet; TaMin_C: -55°C; Polarized: N; SizeAreaWB_mm2: 6.75; Value1: Unknown; U/M: EA; Value: 1uF; TaMax_C: 125°C; SizeZ_mm: 1.45; SizeX_mm: 2; SizeY_mm: 1.25; Cap_Case: 0805; SizeArea_mm2: 2.5; AEC Category: Q200
D3 = CMP-0028882-2: Diode, Schottky, 40 V, 0.75 A, AEC-Q101, SOD-323; Manufacturer: Infineon Technologies; Vf_V: 740mV; Value: 40V; Value1: 0.75A; Value2: 0.74V; Io_A: 750mA; TJmax_C: 150°C; AEC Category: Q101; AEC Qualified: Y; Green_Lifecycle: Not Set; Green_REACh: Incomplete; SizeArea_mm2: 3.645; SizeAreaWB_mm2: 8.695; SizeX_mm: 2.7; SizeY_mm: 1.35; SizeZ_mm: 1
D4 = CMP-0078131-2: LED, Red, SMD; Manufacturer: Lite-On; Type: AlInGaP; Ir_A: 10µA; Angle: 130; Power_TotalModule: 62.5mW; Value2: 2V; Green_Lifecycle: Not Set; Io_A: 20mA; Value1: .0625W; Green_REACh: Incomplete; Vr_V: 5V
D5 = CMP-0002827-3: LED, Green, SMD; Manufacturer: Lite-On; Power_TotalModule: 100mW; Value2: 2.1V; Io_A: 20mA; Value1: 0.1W
J2 = CMP-0055311-1: Receptacle, USB 2.0, Micro B, 5 Position, R/A, SMT; Manufacturer: Molex; CNHeader: FALSE; Current_A: 1.8A; Gender: Female; Voltage_V: 30V; Pitch_mm: 0.65; ContactFinish: Gold; CT: TRUE; Cert_UL: Y
J3 J5 = CMP-0002334-1: as J1 on sheet MD078A_CONTROL
J4 = CMP-0075409-2: Header, 100mil, 4x1, Gold, TH; Manufacturer: Samtec; Pitch_mm: 2.54; Cert_VDE: N; Gender: Male; Cert_CSA: Y; Voltage_V: 550V; Green_REACh: Passed; Current_A: 6.3A; Green_Lifecycle: Active; Row_Count: 1
J6 = CMP-0075464-1: Header, 100mil, 9x2, Gold, TH; Manufacturer: Samtec; Pitch_mm: 2.54; Cert_VDE: N; Gender: Male; Cert_CSA: Y; Voltage_V: 550V; Green_REACh: Passed; Current_A: 6.3A; CT: False; Green_Lifecycle: Active; Row_Count: 2; CNHeader: True
L1 = CMP-0084877-1: Inductor, Ferrite Bead, Ferrite, 3 A, 120 ohm, AEC-Q200 Grade 1, SMD; Manufacturer: MuRata; SizeX_mm: 1.6; AEC Grade: 1; Value2: 3A; SizeY_mm: 0.8; SizeAreaWB_mm2: 4.68; SizeArea_mm2: 1.28; AEC Qualified: Y; AEC Category: Q200
R24 = CMP-0025925-5: RES, 47 k, 5%, 0.1 W, 0603; Manufacturer: Yageo; Power_W: 100mW; TempCo: 100 ppm/C; Value_Code: 47k0; Value: 47k; EIA_Code: E24; SizeX_mm: 1.6; SizeY_mm: 0.8; SizeZ_mm: 1; Value2: 0.1W; SizeArea_mm2: 1.28; AEC Qualified: N; VDC_V: 75V; AEC Category: Q200; SizeAreaWB_mm2: 4.68
R25 R26 = CMP-0025924-5: RES, 470, 5%, 0.1 W, 0603; Manufacturer: Yageo; Power_W: 100mW; TempCo: 100 ppm/C; Value_Code: 470R; Value: 470; EIA_Code: E24; SizeX_mm: 1.6; SizeY_mm: 0.8; SizeZ_mm: 1; Value2: 0.1W; SizeArea_mm2: 1.28; AEC Qualified: N; VDC_V: 75V; AEC Category: Q200; SizeAreaWB_mm2: 4.68
S3 = CMP-0002196-2: Switch, Tactile, SPST, 12 V, SMD; PartNumber: 434121025816; Manufacturer: Wurth Elektronik; VDC_V: 12V; SwitchFunction: Off-On; PositionCount: 1; CurrentRating_mA: 50A
SH-J2-SH-J12 = CMP-0003623-3: as SH-J1 on sheet MD078A_CONTROL
TP10-TP14 = CMP-0055137-2: as TP5 on sheet MD078A_DRIVER
U2 = CMP-0121693-1: UART Interface IC USB Full Speed to Serial UART IC, Includes Oscillator and EEPROM, SSOP-28; Manufacturer: FTDI; SizeZ_mm: 2mm; AEC Qualified: No; Data Rate: 3Mbits/s; Interface: UART,USB; Max Supply Voltage: 5.25V; Min Supply Voltage: 1.8V; Nominal Supply Current: 7mA; Number Of Ports: 1; Standoff Height: 0.05mm; TaMax_C: +85°C; TaMin_C: -40°C; Usb Standard: USB 2.0
U3 = CMP-0043115-3: 4-Channel ESD Protection Array for High-Speed Data Interfaces, DRY0006A (USON-6); Manufacturer: Texas Instruments; IO Leakage Current(nA): 1; USB High Speed: TRUE; IO Capacitance(Typ)(pF): 1.6; Eco-Plan: Green (RoHS & no Sb/Br); IEC 61000-4-2 Contact(+/- kV): 8; Breakdown Voltage(Min)(V): 6; IEC 61000-4-2 Air-Gap(+/- kV): 12; AEC Category: Q200; AEC Qualified: N; CompType: IC; SizeAreaWB_mm2: 4.9; SizeArea_mm2: 1.45; SizeX_mm: 1.0; SizeZ_mm: 0.6; Rating: Catalog
U4 = CMP-0089204-1: CPU16 MSP430™ FRAM Microcontroller IC 16-Bit 24MHz 32KB (32K x 8) FRAM 48-LQFP (7x7); Manufacturer: Texas Instruments; Memory Type: OTHER; Data Bus Width: 16bits; Number Of Spi Channels: 4; Number Of I/Os: 44; Number Of Uart Channels: 2; AEC Qualified: No; Standoff Height: 0.05mm; Ram Size: 4KBytes; TaMin_C: -40°C; Core Architecture: RISC; Number Of Adc Channels: 12; SizeZ_mm: 1.6mm; Number Of A/D Converters: 1; Memory Size: 32KBytes; TaMax_C: +105°C; TJmax_C: +115°C; Interface: I2C,SPI,UART,USART,SCI,IrDA; Min Supply Voltage: 1.8V; Max Supply Voltage: 3.6V
Y1 = CMP-0084387-1: Resonator, 4 MHz, 39 pF, AEC-Q200 Grade 1, SMD; Manufacturer: MuRata; Load Capacitance: 39 pF; AEC Qualified: Y; TaMax_C: 125°C; AEC Category: Q200; SizeArea_mm2: 9; SizeZ_mm: 1.2; Frequency_Fixed: 4MHz; SizeAreaWB_mm2: 16.5; SizeY_mm: 2; SizeX_mm: 4.5; TaMin_C: -40°C; AEC Grade: 1

## Sheet MD078A_POWER_AND_CONNECTORS.SchDoc
size 431 x 279 mm; Date: Not shown in title block; ApprovedBy: Not shown in title block; CheckedBy: Not shown in title block; Author: Not shown in title block; CompanyName: Not shown in title block; Engineer: Not shown in title block; Organization: Not shown in title block; Address1: Not shown in title block; Address2: Not shown in title block; Address3: Not shown in title block; Address4: Not shown in title block; DocumentNumber: 5; Revision: Use project parameter SCH_Rev; SheetNumber: 4; SheetTotal: 5; PageSetup: Record=PageOptions¦CenterHorizontal=True¦CenterVertical=True¦PrintScale=1.00¦XCorrection=1.00¦YCorrection=1.00¦PrintKind=0¦BorderSize=5000000¦LeftOffset=0¦BottomOffset=0¦Orientation=2¦PaperLength=1000¦PaperWidth=1000¦Scale=100¦PaperSource=15¦PrintQuality=600¦MediaType=1¦DitherType=10¦PaperKind=Letter¦PrintScaleMode=1
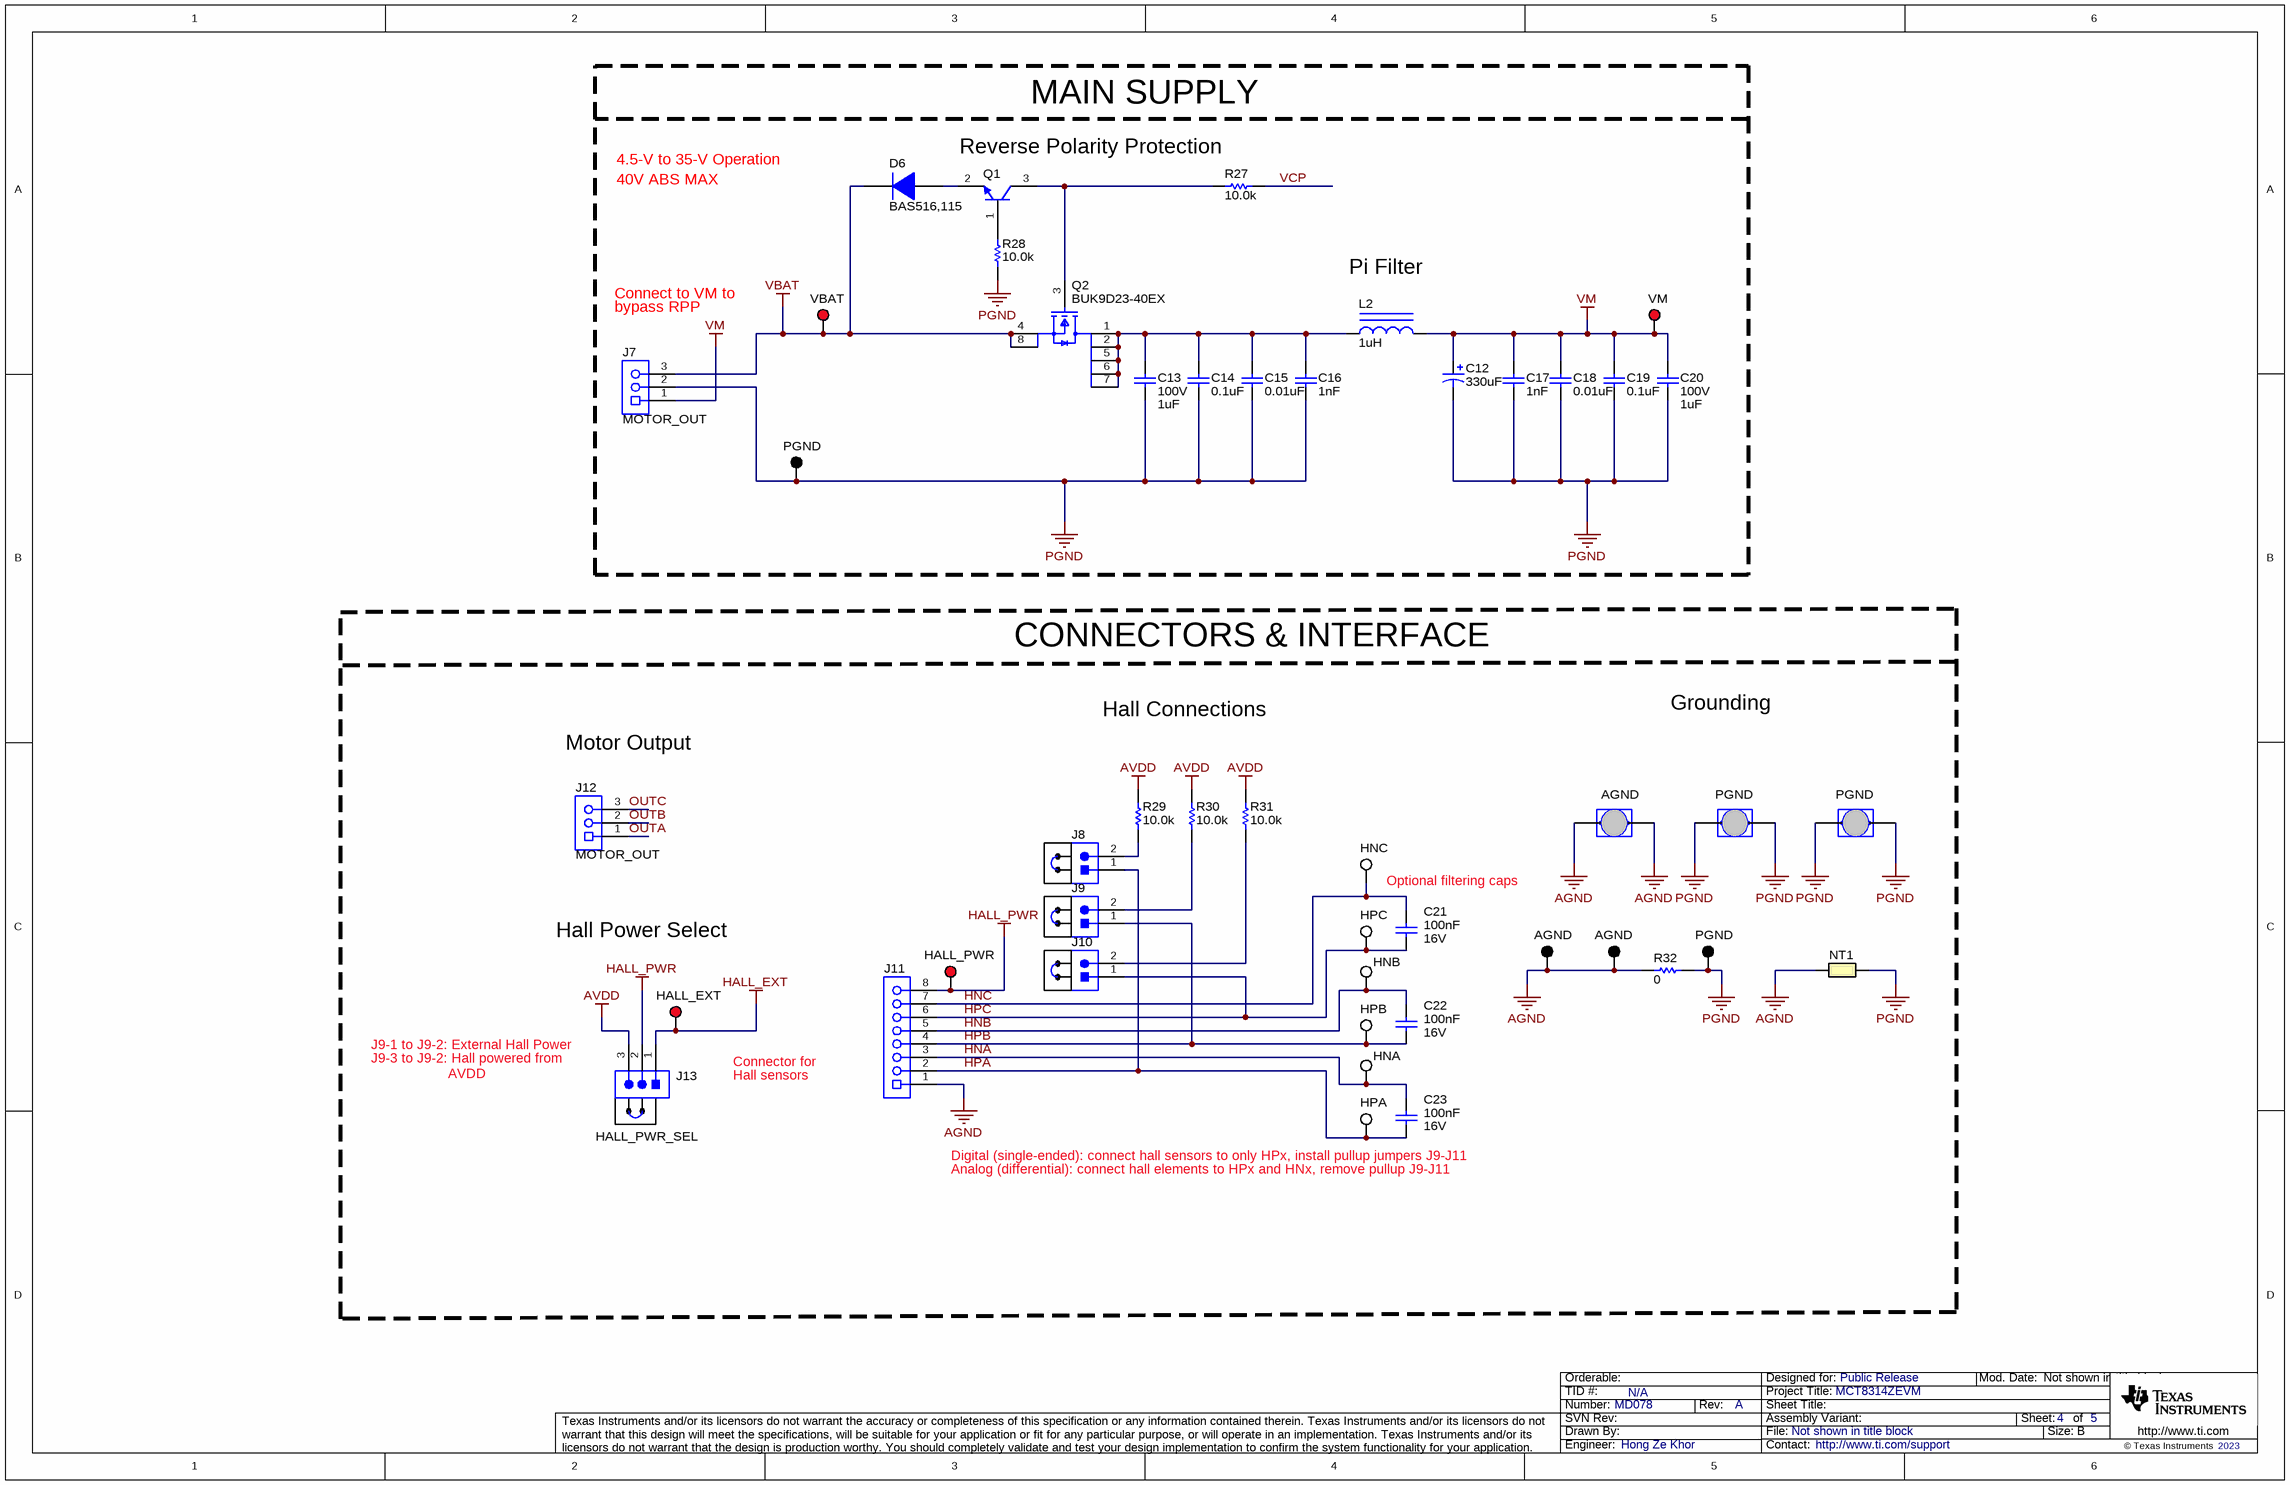
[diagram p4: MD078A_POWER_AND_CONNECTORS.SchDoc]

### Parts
C12  ValueDisplayed: 330uF  [Chemi-Con_1250x2000]  (hidden comment: ELXZ630ELL331MK20S)
C13  VDC_V: 100V  ValueDisplayed: 1uF  [1206_180]  (hidden comment: GRM31CR72A105KA01L)
C14  ValueDisplayed: 0.1uF  [0603L]  (hidden comment: CGA3E3X7S2A104K080AB)
C15  ValueDisplayed: 0.01uF  [0603L]  (hidden comment: CGA3E2X7R2A103K080AA)
C16  Cap_F: 1nF  [0603L]  (hidden comment: 06031C102JAT2A)
C17  Cap_F: 1nF  [0603L]  (hidden comment: 06031C102JAT2A)
C18  ValueDisplayed: 0.01uF  [0603L]  (hidden comment: CGA3E2X7R2A103K080AA)
C19  ValueDisplayed: 0.1uF  [0603L]  (hidden comment: CGA3E3X7S2A104K080AB)
C20  VDC_V: 100V  ValueDisplayed: 1uF  [1206_180]  (hidden comment: GRM31CR72A105KA01L)
C21  Cap_F: 100nF  VDC_V: 16V  [0603L]  (hidden comment: 0603YC104K4T4A)
C22  Cap_F: 100nF  VDC_V: 16V  [0603L]  (hidden comment: 0603YC104K4T4A)
C23  Cap_F: 100nF  VDC_V: 16V  [0603L]  (hidden comment: 0603YC104K4T4A)
D6  BAS516,115  [SOD-523]
J7  MOTOR_OUT  [On-Shore_ED120_3DS]
J8  PEC02SAAN  [CONN_PEC02SAAN]  (value not drawn)
J9  PEC02SAAN  [CONN_PEC02SAAN]  (value not drawn)
J10  PEC02SAAN  [CONN_PEC02SAAN]  (value not drawn)
J11  OSTTE080161  [On-Shore_OSTTE080161]  (value not drawn)
J12  MOTOR_OUT  [On-Shore_ED120_3DS]
J13  HALL_PWR_SEL  [PBC03SAAN]
L2  ValueDisplayed: 1uH  [SRP1038A]  (hidden comment: SRP1038A-1R0M)
NT1  Net-Tie  [Net-Tie_50milWide_30milLong]  (value not drawn)  (net tie, no BOM)
Q1  FMMT620TA  [SOT-23L]  (value not drawn)
Q2  BUK9D23-40EX  [FP-BUK9D23-40EX_SOT1220-MFG]
R27  ValueDisplayed: 10.0k  [0603]  (hidden comment: RC0603FR-0710KL)
R28  ValueDisplayed: 10.0k  [0603]  (hidden comment: RC0603FR-0710KL)
R29  ValueDisplayed: 10.0k  [0603]  (hidden comment: RC0603FR-0710KL)
R30  ValueDisplayed: 10.0k  [0603]  (hidden comment: RC0603FR-0710KL)
R31  ValueDisplayed: 10.0k  [0603]  (hidden comment: RC0603FR-0710KL)
R32  ValueDisplayed: 0  [1206L]  (hidden comment: RCA12060000ZSEA)
SH-J13  SNT-100-BK-G  [SNT-100-BK-G]  (value not drawn)
SH-J14  SNT-100-BK-G  [SNT-100-BK-G]  (value not drawn)
SH-J15  SNT-100-BK-G  [SNT-100-BK-G]  (value not drawn)
SH-J16  SNT-100-BK-G  [SNT-100-BK-G]  (value not drawn)
TP15  VBAT  [Keystone5005]
TP16  VM  [Keystone5005]
TP17  PGND  [Keystone5001]
TP18  AGND  [Harwin_D3082-05]
TP19  PGND  [Harwin_D3082-05]
TP20  PGND  [Harwin_D3082-05]
TP21  HNC  [Keystone5002]
TP22  HPC  [Keystone5002]
TP23  AGND  [Keystone5001]
TP24  AGND  [Keystone5001]
TP25  PGND  [Keystone5001]
TP26  HALL_PWR  [Keystone5000]
TP27  HNB  [Keystone5002]
TP28  HPB  [Keystone5002]
TP29  HNA  [Keystone5002]
TP30  HPA  [Keystone5002]
TP31  HALL_EXT  [Keystone5000]

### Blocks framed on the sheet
MAIN SUPPLY: C12-C20 D6 J7 L2 Q1 Q2 R27 R28 TP15-TP17

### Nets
AGND: J11.1 NT1.1 R32.1 TP18.1 TP18.2 TP23.1 TP24.1
AVDD: J13.3 R29.1 R30.1 R31.1
HALL_EXT: J13.1 TP31.1
HALL_PWR: J11.8 J13.2 TP26.1
PGND: C12.2(-) C13.2 C14.2 C15.2 C16.2 C17.2 C18.2 C19.2 C20.2 J7.2 NT1.2 R28.1 R32.2 TP17.1 TP19.1 TP19.2 TP20.1 TP20.2 TP25.1
VBAT: D6.1(K) J7.3 Q2.4(S) Q2.8(S) TP15.1
VM: C12.1(+) C17.1 C18.1 C19.1 C20.1 J7.1 L2.2 TP16.1
HNA: C23.1 J11.3 TP29.1
HNB: C22.1 J11.5 TP27.1
HNC: C21.1 J11.7 TP21.1
HPA: C23.2 J8.1 J11.2 TP30.1
HPB: C22.2 J9.1 J11.4 TP28.1
HPC: C21.2 J10.1 J11.6 TP22.1
OUTA: J12.1
OUTB: J12.2
OUTC: J12.3
VCP: R27.1
NetC13_1: C13.1 C14.1 C15.1 C16.1 L2.1 Q2.1(D) Q2.2(D) Q2.5(D) Q2.6(D) Q2.7(D)
NetD6_2: D6.2(A) Q1.2(E)
NetJ8_2: J8.2 R29.2
NetJ9_2: J9.2 R30.2
NetJ10_2: J10.2 R31.2
NetQ1_1: Q1.1(B) R28.2
NetQ1_3: Q1.3(C) Q2.3(G) R27.2

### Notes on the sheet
- 4.5-V to 35-V Operation
- Reverse Polarity Protection
- 40V ABS MAX
- bypass RPP
- Connect to VM to
- Pi Filter
- CONNECTORS & INTERFACE
- Hall Connections
- Grounding
- Motor Output
- Optional filtering caps
- Hall Power Select
- (near J13) J9-1 to J9-2: External Hall Power
- J9-3 to J9-2: Hall powered from
- AVDD
- Connector for
- Hall sensors
- Digital (single-ended): connect hall sensors to only HPx, install pullup jumpers J9-J11
- Analog (differential): connect hall elements to HPx and HNx, remove pullup J9-J11

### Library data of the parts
C12 = CMP-0009912-2: CAP, AL, 330 uF, 63 V, +/- 20%, AEC-Q200 Grade 2, TH; Manufacturer: Chemi-Con; Polarized: Y; CompType: Capacitor; Value: 330uF; U/M: EA; Cap_F: 330µF; Value1: Unknown; VDC_V: 63V; IRMS_A: 1.29A; TaMin_C: -55°C; TaMax_C: 105°C; Cap_Case: 12.5x20mm; AEC Category: Q200; AEC Grade: 2; SizeAreaWB_mm2: 210.25; SizeArea_mm2: 156.25; SizeX_mm: 12.5; SizeZ_mm: 21.5
C13 C20 = CMP-0008970-2: CAP, CERM, 1 uF, 100 V, +/- 10%, X7R, 1206; Manufacturer: MuRata; TaMin_C: -55°C; Polarized: N; SizeAreaWB_mm2: 10.92; Value1: Unknown; U/M: EA; Value: 1uF; TaMax_C: 125°C; SizeZ_mm: 1.8; SizeX_mm: 3.2; SizeY_mm: 1.6; Cap_Case: 2220; SizeArea_mm2: 5.12; Cap_F: 1µF; AEC Category: Q200
C14 C19 = CMP-0007099-4: CAP, CERM, 0.1 uF, 100 V, +/- 10%, X7S, AEC-Q200 Grade 1, 0603; Manufacturer: TDK; Polarized: N; Value: 0.1uF; U/M: EA; Cap_F: 100nF; ESR_ohm: 0.04959; Value1: 0.04959 ohm; VDC_V: 100V; IRMS_A: 751.618mA; TaMin_C: -55°C; TaMax_C: 125°C; Cap_Case: 0603; AEC Category: Q200; AEC Qualified: Y; AEC Grade: 1; SizeAreaWB_mm2: 4.68; SizeX_mm: 1.6; SizeY_mm: 0.8; SizeArea_mm2: 1.28
C15 C18 = CMP-0007082-4: CAP, CERM, 0.01 uF, 100 V, +/- 10%, X7R, AEC-Q200 Grade 1, 0603; Manufacturer: TDK; Polarized: N; Value: 0.01uF; U/M: EA; Cap_F: 10nF; ESR_ohm: 0.235428; Value1: 0.235428 ohm; VDC_V: 100V; IRMS_A: 396.995mA; TaMin_C: -55°C; TaMax_C: 125°C; Cap_Case: 0603; AEC Category: Q200; AEC Qualified: Y; AEC Grade: 1; SizeArea_mm2: 1.28; SizeAreaWB_mm2: 4.68; SizeX_mm: 1.6; SizeY_mm: 0.8
C16 C17 = CMP-0006723-4: CAP, CERM, 1000 pF, 100 V, +/- 5%, X7R, 0603; Manufacturer: AVX; TaMin_C: -55°C; ESR_ohm: 2.76d; Polarized: N; SizeAreaWB_mm2: 4.68; Value1: 0.276 ohm; U/M: EA; Value: 1000pF; TaMax_C: 125°C; SizeZ_mm: 1; SizeX_mm: 1.6; SizeY_mm: 0.8; Cap_Case: 0603; Value2: 100V; SizeArea_mm2: 1.28; AEC Category: Q200
C21-C23 = CMP-0083626-1: CAP, CERM, 0.1 µF, 16 V,+/- 10%, X7R, AEC-Q200 Grade 1, 0603; Manufacturer: AVX; SizeAreaWB_mm2: 4.68; SizeArea_mm2: 1.28; AEC Qualified: Y; AEC Category: Q200; Value: 0.1uF; TaMax_C: 125°C; SizeZ_mm: 1; Polarized: N; TaMin_C: -55°C; SizeY_mm: 0.8; U/M: EA; SizeX_mm: 1.6; Cap_Case: 0603; ValueDisplayed: 0.1µF
D6 = CMP-0076979-3: Diode, Switching, 100 V, 0.25 A, SOD-523; Manufacturer: Nexperia; Value: 100V; SizeAreaWB_mm2: 5.13; Vf_V: 1.25V; SizeArea_mm2: 1.53; SizeY_mm: 0.9; Green_Lifecycle: Not Set; AEC Category: Q101; SizeX_mm: 1.7; Green_REACh: Incomplete; Io_A: 250mA; TJmax_C: 150°C; SizeZ_mm: 0.65; Value1: 0.25A
J7 J12 = CMP-0074911-1: Terminal Block, 5.08 mm, 3x1, Brass, TH; Manufacturer: On-Shore Technology; PartNumber: ED120/3DS; Cert_VDE: Y; CNHeader: False; Current_A: 15A; Green_Lifecycle: Not Set; Shrouded: N; Gender: Female; Green_REACh: Incomplete; Voltage_V: 300V; Row_Count: 1; Pitch_mm: 5.08; CT: True
J8-J10 = CMP-0002337-1: Header, 100mil, 2x1, Tin, TH; Manufacturer: Sullins Connector Solutions; CNHeader: TRUE; Current_A: 3A; Green_Lifecycle: Not Set; Shrouded: N; Gender: Male; Green_REACh: Incomplete; Voltage_V: 1.8kV; Row_Count: 1; Pitch_mm: 2.54; CT: FALSE; Cert_UL: Y
J11 = CMP-0074957-2: Terminal Block, 8x1, 3.5mm, TH; Manufacturer: On-Shore Technology; CT: True; Green_REACh: Incomplete; CNHeader: False; Green_Lifecycle: Not Set
J13 = CMP-0002334-1: as J1 on sheet MD078A_CONTROL
L2 = CMP-0056795-1: Inductor, Shielded, Powdered Iron, 1 uH, 18 A, 0.003 ohm, AEC-Q200 Grade 1, SMD; Manufacturer: Bourns; Isat: 36A @ 20% inductance drop; Irms: 18A @ 40C rise; Green_Lifecycle: Active; SizeAreaWB_mm2: 156; DCR_ohm: 3m; Green_REACh: Passed; Value: 1uH; Imax_A: 18A; SizeZ_mm: 4; SizeX_mm: 11; SizeY_mm: 10; SizeArea_mm2: 110; Ind_H: 1µH; AEC Qualified: Y; AEC Grade: 1; AEC Category: Q200
NT1 = CMP-0078142-6: Single point connection between nets.
Q1 = CMP-0000467-2: Transistor, NPN, 80 V, 1.5 A, AEC-Q101, SOT-23; Manufacturer: Diodes Inc.; TaMax_C: 150°C; Value2: 900; Value1: 1.5 A; Vcesat1_V: 160mV; SizeX_mm: 2.5; SizeY_mm: 3; TaMin_C: -55°C; IcRated_A: 1.5A; CompType: BJT; SizeZ_mm: 1.1; AEC Qualified: Y; Value: 80 V; SizeArea_mm2: 7.5; NPN: 1; Vceo_V: 80V; PNP: 0; AEC Category: Q101; SizeAreaWB_mm2: 14; U/M: EA
Q2 = CMP-0088880-1: N-Channel 40V 8A (Ta) 15W (Tc) Surface Mount DFN2020MD-6; Manufacturer: Nexperia; Reverse Recovery Charge: 5.3nC; Vgs_V: 15V; Rthja Max: 57K/W; Number Of N Channels: 1; Pulse Drain Current: 76A; Threshold Vgs Max: 2.1V; Power_W: 2.3W; Reverse Recovery Time: 12.9ns; TaMin_C: -55°C; Rdson45_ohm: 0.018; SizeZ_mm: 0.65mm; ChMode: False; Transconductance: 39S; AEC Qualified: Yes; Typ Forward Diode Voltage: 0.8V; Turn Off Delay Time: 12ns; TaMax_C: +175°C; Input Capacitace At Vds: 637pF @ 20V; QgTyp_nC: 11.5nC @ 10V; Threshold Vgs Min: 1.4V; AEC Grade: Grade 0; VdsMax_V: 1.2V; Turn On Delay Time: 2ns
R27-R31 = CMP-0022746-5: as R1 on sheet MD078A_CONTROL
R32 = CMP-0018760-2: RES, 0, 5%, 0.25 W, AEC-Q200 Grade 0, 1206; Manufacturer: Vishay-Dale; Power_W: 250mW; TempCo: ppm/C; Value_Code: 0000; U/M: EA; Value: 0; EIA_Code: E24; SizeX_mm: 3.2; SizeY_mm: 1.6; SizeZ_mm: 1.35; Value2: 0.25W; SizeArea_mm2: 5.12; AEC Qualified: Y; AEC Category: Q200
SH-J13-SH-J16 = CMP-0003623-3: as SH-J1 on sheet MD078A_CONTROL
TP15 TP16 = CMP-0055142-2: Test Point, Compact, Red, TH; Manufacturer: Keystone Electronics; CNHeader: FALSE; ContactFinish: Silver; CT: TRUE; Green_Lifecycle: Active; Green_REACh: Passed
TP17 TP23-TP25 = CMP-0055138-2: Test Point, Miniature, Black, TH; Manufacturer: Keystone Electronics; CNHeader: FALSE; Green_Lifecycle: Active; Green_REACh: Passed; ContactFinish: Silver; CT: TRUE
TP18-TP20 = CMP-0075110-1: 1mm Uninsulated Shorting Plug, 10.16mm spacing, TH; Manufacturer: Harwin; PartNumber: D3082-05; CNHeader: False; Green_Lifecycle: Active; Green_REACh: Passed; CompType: Jumper Wire
TP21 TP22 TP27-TP30 = CMP-0055139-2: as TP1 on sheet MD078A_CONTROL
TP26 TP31 = CMP-0055137-2: as TP5 on sheet MD078A_DRIVER

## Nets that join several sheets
3V3_MCU: MD078A_CONTROL (R6.1), MD078A_DRIVER (D1.1 R7.2 R8.2 R33.2), MD078A_INTERFACE (9 pins)
AGND: MD078A_CONTROL (R4.1 R5.1 R6.3), MD078A_DRIVER (7 pins), MD078A_INTERFACE (25 pins), MD078A_POWER_AND_CONNECTORS (7 pins)
AVDD: MD078A_CONTROL (R1.2 R2.2), MD078A_DRIVER (5 pins), MD078A_POWER_AND_CONNECTORS (J13.3 R29.1 R30.1 R31.1)
PGND: MD078A_DRIVER (C3.1 C4.2 R20.1 U1.9), MD078A_POWER_AND_CONNECTORS (19 pins)
VM: MD078A_DRIVER (5 pins), MD078A_POWER_AND_CONNECTORS (8 pins)
BRAKE: MD078A_CONTROL (S1.2 TP3.1), MD078A_DRIVER (U1.4)
CLK: MD078A_DRIVER (R10.1), MD078A_INTERFACE (J6.7)
DIR: MD078A_CONTROL (S2.2 TP4.1), MD078A_DRIVER (R14.1)
FGOUT: MD078A_DRIVER (R7.1 TP9.1 U1.6), MD078A_INTERFACE (J6.1)
HNA: MD078A_DRIVER (U1.18), MD078A_POWER_AND_CONNECTORS (C23.1 J11.3 TP29.1)
HNB: MD078A_DRIVER (U1.20), MD078A_POWER_AND_CONNECTORS (C22.1 J11.5 TP27.1)
HNC: MD078A_DRIVER (U1.22), MD078A_POWER_AND_CONNECTORS (C21.1 J11.7 TP21.1)
HPA: MD078A_DRIVER (U1.17), MD078A_POWER_AND_CONNECTORS (C23.2 J8.1 J11.2 TP30.1)
HPB: MD078A_DRIVER (U1.19), MD078A_POWER_AND_CONNECTORS (C22.2 J9.1 J11.4 TP28.1)
HPC: MD078A_DRIVER (U1.21), MD078A_POWER_AND_CONNECTORS (C21.2 J10.1 J11.6 TP22.1)
MSP_POT_P1.1: MD078A_CONTROL (R3.1), MD078A_INTERFACE (U4.2)
MSP_PWM_P2.0: MD078A_CONTROL (J1.3 TP1.1), MD078A_INTERFACE (U4.30)
nFAULT: MD078A_DRIVER (R19.1 U1.13), MD078A_INTERFACE (J6.13)
nSLEEP: MD078A_DRIVER (U1.14), MD078A_INTERFACE (J6.15)
OUTA: MD078A_DRIVER (TP5.1 U1.10), MD078A_POWER_AND_CONNECTORS (J12.1)
OUTB: MD078A_DRIVER (TP6.1 U1.11), MD078A_POWER_AND_CONNECTORS (J12.2)
OUTC: MD078A_DRIVER (TP7.1 U1.12), MD078A_POWER_AND_CONNECTORS (J12.3)
PICO: MD078A_DRIVER (R11.1), MD078A_INTERFACE (J6.9)
POCI: MD078A_DRIVER (R8.1 R12.1), MD078A_INTERFACE (J6.11)
PWM: MD078A_DRIVER (U1.5), MD078A_INTERFACE (J6.3)
PWM_SEL: MD078A_CONTROL (J1.2), MD078A_INTERFACE (J6.4)
STE: MD078A_DRIVER (R13.1 R33.1), MD078A_INTERFACE (J6.5)
VCP: MD078A_DRIVER (C2.2 U1.7), MD078A_POWER_AND_CONNECTORS (R27.1)

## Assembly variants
001: not fitted C21 C22 C23 R14 R16 R17 R18 R21 R22 R23
002: not fitted C21 C22 C23 R10 R11 R12 R13 R16 R22 R23; alternate parts U1 -> CMP-0122133-1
